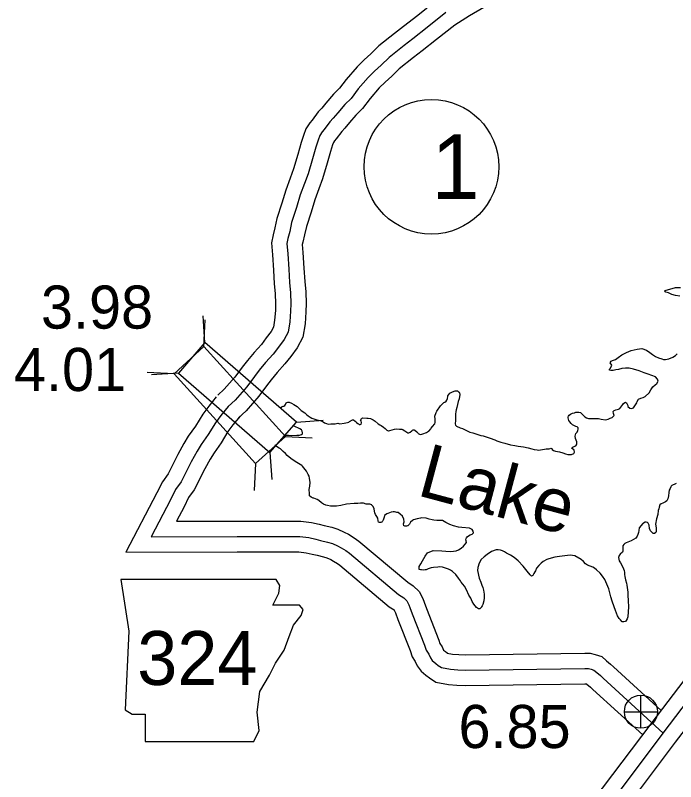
# Model space of a CAD drawing. Extents: x 31699 to 244310, y -8841 to 11474.
# Drawn here: x 97952 to 98384, y 3056 to 3557 of the extents above; entities that cross this region are included whole.
import ezdxf

# ---------------------------------------------------------------- set-up
doc = ezdxf.new("R2010")
doc.units = 0
for name, color, linetype in [('B_Logo', 7, 'Continuous'), ('G-ANNO-TEXT', 7, 'Continuous'), ('Level 21', 7, 'Continuous'), ('Level 55', 7, 'Continuous'), ('R_Border Notes', 7, 'Continuous'), ('R_Draft', 7, 'Continuous'), ('R_XS_EARTHWORK_STAGE1', 7, 'Continuous'), ('S_WALL', 7, 'Continuous'), ('S_WALL_ANNOT', 7, 'Continuous')]:
    doc.layers.add(name, color=color, linetype=linetype)

msp = doc.modelspace()

# ---------------------------------------------------------------- linework, layer by layer
at = {"layer": 'B_Logo'}
for points in [[(98233.72, 3558.33), (98221.56, 3548.62), (98212.12, 3541.26), (98206.48, 3536.91), (98196.65, 3529.01), (98191.53, 3524.06), (98187.22, 3520.11), (98182.97, 3516.03), (98176.4, 3508.41), (98171.82, 3502.26), (98167.63, 3498.25), (98163.06, 3492.83), (98160.2, 3489.35), (98158.01, 3487.01), (98154.16, 3481.93), (98152.9, 3480.39), (98151.31, 3477.98), (98150.26, 3474.98), (98148.87, 3470.5), (98146.56, 3462.69), (98143.72, 3453), (98141.28, 3446.59), (98138.64, 3439.18), (98136.13, 3430.89), (98132.96, 3421.07), (98131.71, 3415.4), (98130.52, 3410.72), (98129.8, 3407.38), (98130.42, 3400.78), (98131.05, 3390.63), (98131.6, 3381.89), (98132.22, 3375.28), (98132.37, 3368.14), (98132.32, 3363.2), (98131.81, 3356.19), (98130.76, 3349.51), (98128.04, 3344.63), (98124.39, 3339.69), (98120.88, 3335.14), (98115.97, 3329.66), (98111.85, 3324.64), (98108.6, 3320.63), (98103.69, 3313.88), (98096.13, 3305.18), (98091.48, 3300.97)], [(98091.48, 3300.97), (98086.77, 3295.08), (98083.12, 3290.34), (98078.41, 3282.72), (98073.84, 3276.03), (98071.18, 3271.69), (98067.34, 3264.8), (98060.79, 3251.77), (98057.07, 3246.62), (98053.76, 3240.01), (98041.18, 3215.89), (98097.44, 3216.07), (98138.32, 3215.96), (98144.18, 3215.24), (98148.71, 3214.25), (98151.91, 3213.45), (98156.5, 3212.39), (98159.63, 3211.4), (98162.97, 3209.87), (98165.23, 3208.67), (98168.44, 3206.81), (98170.7, 3205.15), (98202.8, 3178.12), (98206.2, 3175.85), (98208.21, 3173.92), (98209.48, 3171.46), (98210.15, 3169.59), (98211.69, 3165.45), (98219.81, 3144.91), (98220.81, 3141.71), (98222.55, 3139.11), (98223.62, 3136.64), (98224.89, 3134.98), (98227.1, 3133.11), (98228.83, 3131.71), (98230.96, 3130.38), (98236.76, 3129.26), (98241.62, 3128.94), (98246.48, 3128.68), (98324.58, 3129.78), (98326.91, 3129.72), (98328.64, 3129.32), (98330.57, 3128.66), (98332.37, 3127.13), (98334.84, 3125.07), (98336.58, 3123.47), (98375.89, 3087.57)], [(98338.01, 3037.29), (98375.89, 3087.57), (98401.3, 3120.94)]]:
    msp.add_lwpolyline(points, dxfattribs=at)
at = {"layer": 'G-ANNO-TEXT'}
msp.add_lwpolyline([(98021.42, 3187.98), (98026.5, 3154.14), (98024.24, 3102.83), (98028.75, 3100.01), (98037.21, 3100.01), (98037.21, 3081.96), (98108.27, 3081.96), (98111.65, 3089.29), (98110.52, 3101.13), (98112.22, 3114.67), (98118.42, 3125.38), (98122.37, 3133.28), (98128.01, 3141.74), (98131.39, 3150.76), (98134.21, 3158.09), (98139.28, 3164.29), (98140.41, 3168.24), (98138.16, 3171.06), (98120.67, 3171.06), (98124.62, 3178.96), (98125.19, 3184.03), (98122.85, 3187.93)], close=True, dxfattribs=at)
at = {"layer": 'Level 21'}
for p, q in [((98361.24, 3090.67), (98361.24, 3112.34)), ((98350.41, 3101.5), (98372.08, 3101.5))]:
    msp.add_line(p, q, dxfattribs=at)
msp.add_circle((98361.24, 3101.5), 10.83, dxfattribs=at)
at = {"layer": 'Level 55'}
for points in [[(98227.88, 3566.47), (98215.36, 3556.47), (98206, 3549.16), (98200.29, 3544.77), (98190.02, 3536.52), (98184.68, 3531.35), (98180.38, 3527.41), (98175.7, 3522.92), (98168.59, 3514.67), (98164.29, 3508.9), (98160.34, 3505.1), (98155.37, 3499.23), (98152.68, 3495.95), (98150.35, 3493.46), (98146.31, 3488.12), (98144.85, 3486.33), (98142.29, 3482.47), (98140.76, 3478.12), (98139.3, 3473.4), (98136.97, 3465.51), (98134.24, 3456.2), (98131.9, 3450.05), (98129.13, 3442.3), (98126.58, 3433.88), (98123.3, 3423.69), (98121.98, 3417.7), (98120.79, 3413.01), (98119.7, 3407.99), (98120.45, 3400), (98121.07, 3390), (98121.63, 3381.1), (98122.23, 3374.71), (98122.37, 3368.09), (98122.32, 3363.62), (98121.86, 3357.33), (98121.16, 3352.82), (98119.62, 3350.06), (98116.41, 3345.71), (98113.19, 3341.54), (98108.37, 3336.17), (98104.1, 3330.96), (98100.67, 3326.72), (98095.86, 3320.11), (98088.97, 3312.19), (98084.76, 3308.38)], [(98258.62, 3561.68), (98249.11, 3556.32), (98239.55, 3550.19), (98227.75, 3540.77), (98218.25, 3533.36), (98212.66, 3529.05), (98203.27, 3521.51), (98198.39, 3516.78), (98194.05, 3512.82), (98190.23, 3509.15), (98184.2, 3502.15), (98179.34, 3495.62), (98174.93, 3491.39), (98170.74, 3486.43), (98167.73, 3482.76), (98165.67, 3480.56), (98162.02, 3475.74), (98160.96, 3474.45), (98160.34, 3473.5), (98159.75, 3471.84), (98158.44, 3467.61), (98156.15, 3459.87), (98153.21, 3449.81), (98150.66, 3443.13), (98148.14, 3436.05), (98145.67, 3427.91), (98142.62, 3418.46), (98141.44, 3413.09), (98140.26, 3408.43), (98139.9, 3406.78), (98140.39, 3401.55), (98141.03, 3391.26), (98141.57, 3382.67), (98142.21, 3375.85), (98142.37, 3368.19), (98142.32, 3362.78), (98141.75, 3355.05), (98140.36, 3346.2), (98136.47, 3339.21), (98132.38, 3333.66), (98128.57, 3328.74), (98123.56, 3323.15), (98119.6, 3318.32), (98116.54, 3314.54), (98111.52, 3307.64), (98103.28, 3298.17), (98098.19, 3293.56)], [(98083.67, 3307.22), (98078.9, 3301.26), (98074.88, 3296.02), (98070.03, 3288.17), (98065.44, 3281.46), (98062.55, 3276.73), (98058.51, 3269.49), (98052.21, 3256.98), (98048.49, 3251.82), (98044.86, 3244.56), (98024.65, 3205.83), (98097.44, 3206.07), (98137.69, 3205.96), (98142.49, 3205.37), (98146.43, 3204.51), (98149.58, 3203.73), (98153.86, 3202.74), (98156.02, 3202.05), (98158.55, 3200.9), (98160.38, 3199.93), (98162.95, 3198.44), (98164.52, 3197.28), (98196.79, 3170.1), (98199.91, 3168.03), (98200.08, 3167.87), (98200.29, 3167.46), (98200.76, 3166.15), (98202.36, 3161.87), (98210.37, 3141.57), (98211.7, 3137.34), (98213.74, 3134.3), (98214.93, 3131.55), (98217.6, 3128.05), (98220.73, 3125.4), (98223.03, 3123.55), (98227.25, 3120.92), (98235.47, 3119.32), (98241.03, 3118.95), (98246.29, 3118.68), (98324.51, 3119.78), (98325.61, 3119.75), (98325.93, 3119.48), (98328.24, 3117.55), (98329.82, 3116.1), (98362.43, 3086.32)], [(98099.28, 3294.72), (98094.64, 3288.91), (98091.36, 3284.65), (98086.8, 3277.26), (98082.24, 3270.6), (98079.82, 3266.64), (98076.18, 3260.12), (98069.36, 3246.57), (98065.65, 3241.43), (98062.67, 3235.46), (98057.7, 3225.94), (98097.43, 3226.07), (98138.94, 3225.96), (98145.86, 3225.11), (98150.98, 3223.99), (98154.23, 3223.18), (98159.14, 3222.05), (98163.25, 3220.75), (98167.39, 3218.85), (98170.09, 3217.42), (98173.92, 3215.19), (98176.89, 3213.01), (98208.81, 3186.13), (98212.5, 3183.68), (98216.34, 3179.97), (98218.67, 3175.45), (98219.54, 3173.03), (98221.03, 3169.04), (98229.24, 3148.25), (98229.92, 3146.08), (98231.36, 3143.92), (98232.27, 3141.83), (98233.46, 3140.82), (98234.63, 3139.88), (98234.68, 3139.85), (98238.05, 3139.2), (98242.22, 3138.92), (98246.68, 3138.68), (98324.64, 3139.78), (98328.17, 3139.69), (98331.39, 3138.95), (98335.61, 3137.5), (98338.82, 3134.78), (98341.44, 3132.58), (98343.34, 3130.84), (98374.56, 3102.33)], [(98330.12, 3043.43), (98367.92, 3093.61), (98393.56, 3127.28)], [(98345.91, 3031.16), (98383.86, 3081.53), (98409.04, 3114.59)]]:
    msp.add_lwpolyline(points, dxfattribs=at)
at = {"layer": 'R_Border Notes'}
msp.add_circle((98224.35, 3457.62), 44, dxfattribs=at)
at = {"layer": 'R_Draft'}
for points in [[(98386.69, 3373.02), (98383.89, 3373.55), (98381.5, 3374.21), (98379.3, 3375.14), (98377.63, 3375.67), (98377.16, 3375.81), (98376.9, 3376.47), (98377.03, 3376.74), (98383.75, 3378.76), (98387.14, 3378.7)], [(98318.62, 3287.97), (98317.48, 3288.43), (98316.62, 3288.9), (98315.68, 3289.83), (98314.75, 3290.96), (98314.14, 3291.76), (98313.81, 3292.7), (98313.67, 3293.63), (98313.8, 3294.3), (98313.94, 3294.63), (98314.4, 3295.24), (98315.2, 3295.91), (98316.53, 3296.51), (98317.79, 3296.91), (98318.72, 3297.25), (98320.65, 3297.32), (98321.65, 3296.99), (98322.52, 3296.39), (98323.79, 3295.12), (98324.59, 3294.19), (98325.66, 3293.46), (98326.92, 3293.06), (98328.06, 3293), (98329.39, 3293.07), (98330.72, 3293.07), (98333.52, 3293.07), (98335.31, 3292.74), (98338.11, 3292.28), (98338.18, 3292.28), (98339.84, 3292.75), (98341.17, 3293.22), (98342.37, 3293.76), (98343.7, 3295.1), (98343.49, 3295.7), (98343.23, 3296.3), (98343.02, 3297.77), (98343.69, 3298.44), (98344.82, 3298.77), (98346.55, 3299.11), (98347.48, 3299.65), (98348.21, 3300.45), (98348.87, 3301.38), (98349.47, 3302.25), (98349.93, 3302.92), (98350.66, 3303.46), (98351.26, 3303.73), (98351.86, 3303.39), (98352.47, 3302.13), (98352.6, 3301.53), (98352.8, 3300.86), (98354.07, 3299.93), (98354.87, 3299.66), (98355.8, 3299.8), (98356.47, 3300.13), (98357.79, 3301.94), (98358.59, 3303.41), (98358.85, 3304.21), (98359.65, 3305.81), (98361.18, 3306.48), (98362.64, 3306.89), (98364.04, 3307.42), (98366.63, 3309.9), (98367.62, 3311.84), (98369.01, 3313.84), (98370.47, 3315.11), (98371.74, 3315.98), (98372.46, 3317.59), (98372.13, 3318.72), (98370.79, 3320.32), (98366.06, 3322.18), (98363.46, 3323.04), (98360.19, 3324.3), (98356.4, 3325.36), (98353.53, 3325.96), (98351.27, 3325.95), (98348.81, 3325.68), (98346.68, 3325.21), (98344.95, 3324.81), (98343.15, 3324.53), (98341.55, 3324.46), (98340.75, 3324.66), (98340.82, 3325.26), (98341.28, 3326), (98342.27, 3327.94), (98341.87, 3328.54), (98341.61, 3328.8), (98341.07, 3329.54), (98341.8, 3330.47), (98342.73, 3330.94), (98344.53, 3331.61), (98346.39, 3332.89), (98348.85, 3334.63), (98351.77, 3336.3), (98354.9, 3337.51), (98358.76, 3338.39), (98361.95, 3338.79), (98364.95, 3337.8), (98367.09, 3336.2), (98368.89, 3334.87), (98370.82, 3333.6), (98372.82, 3332.74)], [(98372.82, 3332.74), (98374.95, 3332.08), (98376.02, 3331.75), (98377.35, 3331.75), (98379.48, 3332.09), (98382.14, 3333.16), (98383.74, 3334.37), (98385, 3335.37)], [(98226.58, 3294.65), (98227.51, 3296.99), (98227.91, 3297.79), (98230.23, 3301.33), (98231.29, 3302.47), (98232.49, 3303.47), (98233.02, 3303.81), (98233.88, 3304.54), (98234.41, 3305.14), (98234.68, 3305.55), (98234.88, 3306.08), (98234.87, 3306.35), (98235.01, 3307.35), (98235.14, 3307.82), (98235.67, 3308.88), (98236.46, 3309.69), (98238.13, 3310.49), (98238.86, 3310.76), (98239.19, 3310.96), (98239.86, 3311.1), (98240.85, 3311.23), (98241.32, 3311.1), (98241.85, 3310.83), (98242.12, 3310.43), (98242.39, 3310.23), (98242.66, 3309.57), (98242.79, 3309.17), (98242.79, 3308.5), (98242.73, 3307.57), (98242.4, 3306.03), (98241.74, 3304.23), (98241.28, 3302.29), (98240.95, 3300.29), (98240.49, 3298.82), (98240.23, 3297.68), (98240.03, 3295.88), (98240.1, 3294.48), (98240.04, 3292.34), (98239.98, 3291.14), (98239.85, 3290.34), (98239.91, 3289.54), (98240.12, 3288.74), (98240.65, 3288.14), (98243.18, 3286.94), (98244.58, 3286.54), (98249.45, 3284.15), (98251.38, 3283.75), (98256.58, 3282.1), (98258.05, 3281.7), (98260.84, 3280.97), (98262.71, 3280.17), (98265.78, 3279.11), (98267.18, 3278.51), (98269.71, 3277.65), (98272.37, 3276.92), (98275.9, 3276), (98278.9, 3275.4), (98280.97, 3275.07), (98284.56, 3274.55), (98287.49, 3273.95), (98289.89, 3273.36), (98291.49, 3272.76), (98293.36, 3272.56), (98294.62, 3272.5), (98295.69, 3272.7), (98298.15, 3272.97), (98299.28, 3273.18), (98300.81, 3273.25), (98301.35, 3273.38), (98301.88, 3273.52), (98302.34, 3273.78), (98302.94, 3273.52), (98303.34, 3272.85), (98304.08, 3272.25), (98305.41, 3271.79), (98308.08, 3271.33), (98310.14, 3270.73), (98312.01, 3270.07), (98313.47, 3269.67), (98315.8, 3269.67), (98317.47, 3270.28), (98317.73, 3271.01), (98317.59, 3272.48), (98316.39, 3273.41), (98316.19, 3273.55), (98316.26, 3274.15), (98316.99, 3274.62), (98318.72, 3275.35), (98319.25, 3275.82), (98319.45, 3276.42), (98319.31, 3277.82), (98318.84, 3278.89), (98318.5, 3280.03), (98318.37, 3281.63), (98318.7, 3283.23), (98319.56, 3284.23), (98320.02, 3285.24), (98320.28, 3286.24), (98320.28, 3287.04), (98319.68, 3287.64), (98318.62, 3287.97)], [(98125.81, 3299.84), (98126.03, 3300.17), (98126.5, 3300.71), (98127.36, 3301.11), (98127.96, 3301.25), (98128.49, 3301.51), (98128.96, 3302.25)], [(98128.96, 3302.25), (98129.42, 3303.25), (98129.82, 3303.65), (98130.42, 3303.85), (98131.42, 3303.72), (98132.88, 3303.06), (98134.42, 3302.19), (98136.55, 3300.86), (98138.09, 3299.33), (98139.09, 3298.33), (98141.62, 3296.74), (98142.09, 3296.34), (98142.62, 3295.8), (98143.76, 3294.87), (98143.83, 3294.87), (98145.03, 3293.87), (98146.23, 3293.34), (98148.83, 3292.35), (98149.69, 3292.15), (98152.22, 3291.55), (98153.16, 3291.15), (98153.49, 3290.95), (98154.42, 3290.35), (98155.69, 3289.76), (98156.82, 3289.49), (98158.55, 3289.56), (98159.29, 3289.7), (98161.48, 3289.57), (98163.21, 3289.97), (98164.48, 3289.71), (98167.21, 3290.11), (98169.47, 3290.39), (98170.27, 3290.66), (98170.8, 3291.06), (98171.6, 3291.59), (98171.93, 3291.79), (98172.2, 3291.99), (98172.79, 3292.33), (98173.39, 3292.13), (98174.4, 3291.47), (98175.06, 3291), (98175.46, 3290.6), (98176.26, 3289.87), (98176.6, 3289.53), (98177.13, 3289.2), (98177.66, 3289.14), (98178.46, 3289.47), (98178.53, 3290.27), (98178.32, 3291.61), (98178.05, 3292.27), (98178.32, 3292.74), (98178.65, 3293.08), (98179.32, 3293.48), (98182.05, 3293.42), (98182.98, 3293.35), (98184.51, 3293.02), (98186.31, 3292.23), (98187.51, 3291.29), (98189.58, 3289.7), (98190.51, 3289.03), (98191.38, 3288.43), (98192.92, 3287.43), (98194.12, 3286.57), (98194.65, 3285.83), (98195.12, 3285.44), (98196.05, 3285.04), (98196.32, 3285.04), (98197.25, 3285.24), (98198.58, 3285.64), (98200.18, 3286.05), (98201.57, 3286.25), (98203.5, 3286.19), (98204.9, 3286.06), (98205.7, 3285.86), (98206.57, 3285.33), (98206.97, 3284.99), (98208.9, 3283.8), (98209.57, 3283.73), (98210.37, 3284.2), (98211.43, 3285), (98211.9, 3285.4), (98212.36, 3285.74), (98212.96, 3285.74), (98213.43, 3285.47), (98214.89, 3284.41), (98215.43, 3283.74), (98215.76, 3283.41), (98216.63, 3282.88), (98217.5, 3282.75), (98218.69, 3283.15), (98221.02, 3284.02), (98222.35, 3284.76), (98222.88, 3285.09), (98223.88, 3286.3), (98224.21, 3286.83), (98225.07, 3287.77), (98226.6, 3289.64), (98226.73, 3290.51), (98226.86, 3291.71), (98226.79, 3292.65), (98226.58, 3294.65)], [(98127.81, 3282.22), (98130.81, 3282.16), (98132.81, 3282.1), (98136.27, 3282.17), (98136.34, 3282.17), (98137.67, 3282.18), (98138.13, 3282.31), (98139.33, 3282.71), (98140, 3282.98), (98140, 3283.65), (98139.79, 3284.78), (98139.32, 3285.72), (98138.32, 3286.45), (98134.72, 3288.18), (98133.68, 3288.36)], [(98187.75, 3230.35), (98187.28, 3231.48), (98187.14, 3232.48), (98186.94, 3234.09), (98186.27, 3235.55), (98185.33, 3236.49), (98185.33, 3236.62), (98184, 3237.22), (98181.6, 3237.08), (98179.87, 3237.74), (98177.94, 3237.81), (98176.14, 3237.67), (98173.74, 3237.53), (98168.82, 3237.18), (98165.03, 3236.31), (98162.3, 3235.77), (98159.97, 3235.76), (98158.37, 3235.83), (98156.44, 3236.22), (98155.24, 3236.49), (98153.77, 3237.22), (98152.57, 3238.02), (98150.84, 3239.48), (98149.57, 3240.15), (98147.37, 3241.08), (98147.04, 3241.14), (98145.7, 3241.74), (98144.64, 3242.54), (98144.56, 3244.14), (98144.42, 3246.81), (98144.88, 3248.95), (98145.08, 3251.22), (98144.67, 3254.15), (98144.4, 3255.49), (98143.8, 3256.42), (98142.59, 3258.62), (98140.12, 3262.02), (98139.72, 3262.29), (98136.39, 3264.28), (98133.92, 3265.81), (98132.45, 3267.01), (98130.12, 3268.94), (98128.91, 3270.14), (98127.51, 3271.47), (98125.64, 3273.2), (98125.71, 3273.2), (98124.84, 3273.74), (98123.04, 3274.87), (98121.95, 3275.75)], [(98384.3, 3250.6), (98382.97, 3249.93), (98382.3, 3249.66), (98381.51, 3249.25), (98381.04, 3248.99), (98380.78, 3248.45), (98380.31, 3247.38), (98379.78, 3246.31), (98379.39, 3244.78), (98379.19, 3242.51), (98378.8, 3240.64), (98378.27, 3239.24), (98377.41, 3238.63), (98376.54, 3238.3), (98375.61, 3237.89), (98374.48, 3237.29), (98373.68, 3236.62), (98373.09, 3235.09), (98372.96, 3234.15), (98372.56, 3233.02), (98372.37, 3230.28), (98371.38, 3227.47), (98370.79, 3224), (98371.13, 3221.66), (98371.27, 3219.33), (98371, 3218.59), (98370.21, 3218.06), (98369.27, 3217.99), (98368.81, 3218.32), (98367.41, 3219.72), (98366.8, 3221.19), (98366.53, 3223.32), (98365.93, 3224.79), (98365.53, 3225.12), (98364.66, 3225.46), (98364.13, 3225.32), (98363, 3224.78), (98362.6, 3224.52), (98360.21, 3221.64), (98359.88, 3219.97), (98359.62, 3218.57), (98359.22, 3217.3), (98358.76, 3216.16), (98357.83, 3214.96), (98356.5, 3214.02), (98354.77, 3213.22), (98353.78, 3212.75), (98352.71, 3212.35), (98351.71, 3211.88), (98350.78, 3211.41), (98350.05, 3210.81), (98349.39, 3209.8), (98349.46, 3209.14), (98349.46, 3207.93), (98349.47, 3206.6), (98349.47, 3206.4), (98349.14, 3205.66), (98347.67, 3204.53), (98347.08, 3203.52), (98346.68, 3202.19), (98347.09, 3200.19), (98347.89, 3198.79), (98349.43, 3195.92), (98350.37, 3193.85), (98350.57, 3192.45)], [(98238.12, 3193.14), (98236.85, 3194.01), (98235.58, 3194.74), (98232.98, 3195.54), (98231.65, 3195.93), (98229.72, 3196.13), (98228.45, 3196.06), (98225.72, 3195.79), (98224.06, 3195.58), (98222.13, 3194.78), (98220.8, 3194.31), (98220.34, 3194.17), (98219.47, 3194.04), (98217.81, 3194.3), (98217.14, 3194.17), (98216.34, 3194.43), (98216.27, 3195.17), (98216.4, 3196.37), (98217.46, 3198.11), (98218.59, 3200.04), (98220.24, 3203.05), (98221.84, 3205.39), (98225.56, 3206.87), (98231.22, 3206.68), (98233.68, 3206.42), (98237.01, 3206.29), (98240.41, 3206.7), (98241.94, 3207.3), (98243.8, 3208.44), (98245.39, 3209.58), (98246.46, 3210.92), (98247.18, 3212.05), (98247.05, 3213.12), (98246.85, 3213.92), (98247.11, 3214.66), (98247.31, 3215.12), (98247.71, 3215.79), (98248.5, 3216.53), (98249.63, 3217.13), (98250.96, 3217.54), (98251.7, 3218.14), (98251.83, 3218.41), (98251.69, 3219.47), (98250.89, 3220.47), (98249.22, 3221.34), (98244.3, 3221.79), (98241.96, 3222.19), (98238.7, 3222.98), (98236.3, 3223.91), (98233.83, 3225.18), (98231.63, 3226.37), (98230.23, 3226.37), (98228.9, 3226.5), (98227.9, 3226.43), (98225.84, 3226.69), (98224.71, 3226.96), (98222.91, 3227.35), (98220.91, 3227.95), (98217.71, 3228.28), (98217.18, 3228.08), (98216.05, 3227.81), (98214.98, 3227.47), (98212.66, 3226.87), (98212.06, 3226.53), (98210.73, 3225.26), (98210, 3224.06), (98209.2, 3223.19), (98209, 3223.05), (98208.67, 3222.92), (98208.07, 3222.72), (98207.01, 3222.65), (98206.41, 3222.91), (98206.21, 3223.05), (98206.14, 3224.18), (98206.6, 3225.58), (98206.4, 3227.39), (98205.33, 3229.19), (98203.86, 3230.52), (98202.59, 3231.65), (98201.79, 3231.78), (98201.06, 3231.91), (98200.12, 3232.11), (98199.26, 3232.18), (98197.93, 3231.84), (98197, 3231.5), (98195.8, 3231.1), (98195.2, 3230.83), (98193.67, 3229.7), (98193.41, 3228.69), (98192.95, 3227.42), (98192.68, 3226.69), (98192.48, 3226.22), (98192.15, 3225.82), (98191.82, 3225.42), (98191.22, 3225.08), (98190.42, 3225.08), (98189.76, 3225.28), (98189.42, 3226.22), (98189.22, 3228.02), (98188.61, 3229.15), (98187.75, 3230.35)], [(98350.57, 3192.45), (98350.57, 3191.12), (98350.64, 3189.78), (98351.18, 3187.71), (98351.79, 3185.44), (98351.99, 3184.18), (98352.67, 3179.64), (98352.67, 3177.77), (98352.95, 3173.97), (98353.16, 3170.09), (98352.97, 3166.69), (98352.65, 3163.55), (98352.32, 3162.22), (98351.65, 3161.08), (98351.12, 3160.48), (98350.06, 3160.14), (98348.99, 3160.21), (98347.93, 3161.47), (98347.06, 3162.47), (98345.99, 3164.27), (98344.65, 3167.74), (98343.77, 3170.07), (98342.5, 3173.81), (98341.69, 3176.54), (98340.35, 3181.88), (98337.73, 3187.82), (98336.19, 3190.15), (98334.59, 3191.95), (98332.19, 3194.15), (98330.85, 3195.35), (98329.85, 3195.88), (98328.12, 3196.61), (98326.25, 3197.34), (98325.05, 3198.2), (98323.79, 3199.6), (98322.18, 3201.07), (98317.98, 3203.33), (98314.92, 3203.72), (98311.59, 3203.45), (98308.13, 3203.04), (98305, 3202.5), (98301.14, 3201.36), (98299.81, 3200.89), (98297.42, 3199.61), (98296.02, 3198.54), (98294.56, 3197.14), (98293.04, 3195.26), (98292.24, 3193.46), (98291.98, 3192.93), (98291.25, 3191.79), (98290.98, 3191.32), (98290.85, 3190.92), (98290.59, 3190.59), (98290.19, 3190.32), (98289.72, 3190.18), (98288.92, 3190.85), (98286.98, 3193.45), (98284.25, 3196.71), (98280.97, 3200.11), (98278.5, 3202.24), (98275.97, 3203.84), (98273.44, 3205.1), (98272.04, 3205.9), (98270.84, 3206.7), (98269.37, 3207.03), (98267.97, 3207.29), (98266.57, 3207.22), (98263.65, 3206.28), (98260.66, 3204.27), (98258.73, 3202.8), (98256.8, 3200.93), (98255.54, 3198.66), (98254.69, 3195.78), (98254.36, 3193.71), (98255.5, 3188.84), (98256.58, 3186.24), (98257.38, 3184.11), (98257.85, 3182.57), (98258.32, 3180.84), (98258.73, 3178.24), (98258.8, 3175.97), (98258.61, 3173.9), (98257.95, 3171.63), (98257.55, 3170.76), (98257.15, 3170.09), (98256.95, 3169.82), (98256.62, 3169.35), (98255.96, 3168.75), (98255.16, 3168.68), (98253.83, 3169.55), (98252.09, 3171.81), (98251.02, 3173.61), (98250.01, 3175.61), (98248.88, 3177.61), (98247.27, 3181.22), (98245.93, 3183.48), (98243.86, 3186.08), (98243.26, 3186.95), (98242.12, 3188.88), (98240.18, 3191.28), (98238.12, 3193.14)]]:
    msp.add_lwpolyline(points, dxfattribs=at)
at = {"layer": 'R_XS_EARTHWORK_STAGE1'}
for p, q in [((98076.31, 3342.73), (98075.09, 3360.28)), ((98075.67, 3340.09), (98076.53, 3357.67)), ((98056.11, 3322.36), (98038.54, 3323.22)), ((98058.97, 3322.81), (98041.42, 3321.59)), ((98136.05, 3290.73), (98153.61, 3291.95)), ((98128.87, 3281.42), (98146.45, 3280.56)), ((98118.72, 3270.82), (98119.93, 3253.26)), ((98109.31, 3263.68), (98108.45, 3246.1))]:
    msp.add_line(p, q, dxfattribs=at)
for points in [[(98128.87, 3281.42), (98075.67, 3340.09), (98056.11, 3322.36), (98109.31, 3263.68)], [(98136.05, 3290.73), (98076.31, 3342.73), (98058.97, 3322.81), (98118.72, 3270.82)]]:
    msp.add_lwpolyline(points, close=True, dxfattribs=at)

# ---------------------------------------------------------------- texts
at = {"layer": 'G-ANNO-TEXT'}
msp.add_text('324', height=35.2, dxfattribs=at).set_placement((98032.06, 3119.01))
at = {"layer": 'R_Border Notes'}
msp.add_text('1', height=42.24, dxfattribs=at).set_placement((98224.35, 3436.5))
at = {"layer": 'R_Draft'}
msp.add_text('Lake', height=35.2, rotation=345, dxfattribs=at).set_placement((98214.01, 3243.18))
at = {"layer": 'S_WALL'}
for s, p in [('3.98', (97969.13, 3351.83)), ('4.01', (97951.51, 3311.07))]:
    msp.add_text(s, height=28.16, dxfattribs=at).set_placement(p)
at = {"layer": 'S_WALL_ANNOT'}
msp.add_text('6.85', height=28.16, dxfattribs=at).set_placement((98242.03, 3077.77))

doc.saveas('drawing.dxf')
